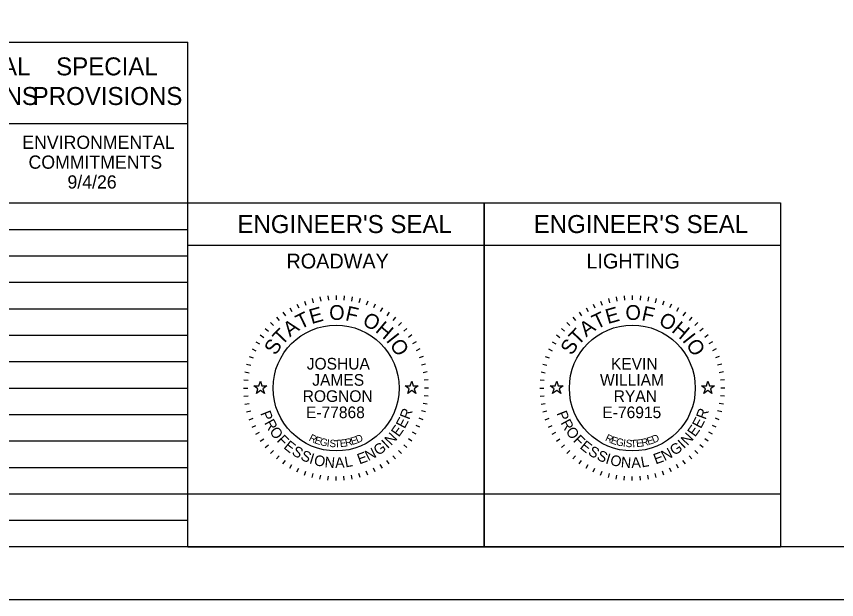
# Model space of a CAD drawing. Extents: x 0 to 34, y 0 to 22.
# Drawn here: x 21.98 to 29.73, y 0 to 5.51 of the extents above; entities that cross this region are included whole.
import ezdxf

# ---------------------------------------------------------------- set-up
doc = ezdxf.new("R2010")
doc.units = 0
for name, color, linetype in [('SH_Border', 7, 'Continuous'), ('SH_Cut_Line', 7, 'Continuous'), ('SH_Data', 7, 'Continuous'), ('SH_Seal', 7, 'Continuous'), ('SH_Text', 7, 'Continuous')]:
    doc.layers.add(name, color=color, linetype=linetype)

msp = doc.modelspace()

# ---------------------------------------------------------------- linework, layer by layer
at = {"layer": 'SH_Border'}
msp.add_lwpolyline([(1.5, 21.5), (33.5, 21.5), (33.5, 0.5), (1.5, 0.5)], close=True, dxfattribs=at)
at = {"layer": 'SH_Cut_Line'}
msp.add_lwpolyline([(0, 0), (34, 0), (34, 22), (0, 22)], close=True, dxfattribs=at)
at = {"layer": 'SH_Data'}
for p, q in [((10.15, 5.2708), (23.6, 5.2708)), ((23.6, 0.5), (23.6, 5.2708)), ((10.15, 4.5), (23.6, 4.5)), ((10.15, 3.75), (23.6, 3.75)), ((23.6, 0.5), (23.6, 3.75)), ((23.6, 3.75), (26.4, 3.75)), ((26.4, 3.75), (26.4, 0.5)), ((26.4, 0.5), (26.4, 3.75)), ((26.4, 3.75), (29.2, 3.75)), ((29.2, 3.75), (29.2, 0.5)), ((10.15, 3.5), (23.6, 3.5)), ((23.6, 3.35), (26.4, 3.35)), ((26.4, 3.35), (29.2, 3.35)), ((10.15, 3.25), (23.6, 3.25)), ((10.15, 3), (23.6, 3)), ((10.15, 2.75), (23.6, 2.75)), ((10.15, 2.5), (23.6, 2.5)), ((10.15, 2.25), (23.6, 2.25)), ((10.15, 2), (23.6, 2)), ((10.15, 1.75), (23.6, 1.75)), ((10.15, 1.5), (23.6, 1.5)), ((10.15, 1.25), (23.6, 1.25)), ((10.15, 1), (23.6, 1)), ((10.15, 0.75), (23.6, 0.75)), ((23.6, 0.5), (26.4, 0.5)), ((26.4, 0.5), (29.2, 0.5))]:
    msp.add_line(p, q, dxfattribs=at)
for points in [[(23.6, 0.5), (23.6, 1), (26.4, 1), (26.4, 0.5)], [(26.4, 0.5), (26.4, 1), (29.2, 1), (29.2, 0.5)]]:
    msp.add_lwpolyline(points, close=True, dxfattribs=at)
at = {"layer": 'SH_Seal'}
for p, q in [((24.9237, 2.8717), (24.9272, 2.8318)), ((25, 2.875), (25, 2.835)), ((25.0763, 2.8717), (25.0728, 2.8318)), ((27.7237, 2.8717), (27.7272, 2.8318)), ((27.8, 2.875), (27.8, 2.835)), ((27.8763, 2.8717), (27.8728, 2.8318)), ((24.6302, 2.793), (24.6471, 2.7568)), ((24.7007, 2.8222), (24.7144, 2.7846)), ((24.7735, 2.8452), (24.7839, 2.8065)), ((24.8481, 2.8617), (24.855, 2.8223)), ((25.1519, 2.8617), (25.145, 2.8223)), ((25.2265, 2.8452), (25.2161, 2.8065)), ((25.2993, 2.8222), (25.2856, 2.7846)), ((25.3698, 2.793), (25.3529, 2.7568)), ((27.4302, 2.793), (27.4471, 2.7568)), ((27.5007, 2.8222), (27.5144, 2.7846)), ((27.5735, 2.8452), (27.5839, 2.8065)), ((27.6481, 2.8617), (27.655, 2.8223)), ((27.9519, 2.8617), (27.945, 2.8223)), ((28.0265, 2.8452), (28.0161, 2.8065)), ((28.0993, 2.8222), (28.0856, 2.7846)), ((28.1698, 2.793), (28.1529, 2.7568)), ((24.4981, 2.7168), (24.5211, 2.684)), ((24.5625, 2.7578), (24.5825, 2.7231)), ((25.4375, 2.7578), (25.4175, 2.7231)), ((25.5019, 2.7168), (25.4789, 2.684)), ((27.2981, 2.7168), (27.3211, 2.684)), ((27.3625, 2.7578), (27.3825, 2.7231)), ((28.2375, 2.7578), (28.2175, 2.7231)), ((28.3019, 2.7168), (28.2789, 2.684)), ((24.4376, 2.6703), (24.4633, 2.6396)), ((25.5624, 2.6703), (25.5367, 2.6396)), ((27.2376, 2.6703), (27.2633, 2.6396)), ((28.3624, 2.6703), (28.3367, 2.6396)), ((24.3297, 2.5624), (24.3604, 2.5367)), ((24.3813, 2.6187), (24.4096, 2.5904)), ((25.6187, 2.6187), (25.5904, 2.5904)), ((25.6703, 2.5624), (25.6396, 2.5367)), ((27.1297, 2.5624), (27.1604, 2.5367)), ((27.1813, 2.6187), (27.2096, 2.5904)), ((28.4187, 2.6187), (28.3904, 2.5904)), ((28.4703, 2.5624), (28.4396, 2.5367)), ((24.2832, 2.5019), (24.316, 2.4789)), ((25.7168, 2.5019), (25.684, 2.4789)), ((27.0832, 2.5019), (27.116, 2.4789)), ((28.5168, 2.5019), (28.484, 2.4789)), ((24.2422, 2.4375), (24.2769, 2.4175)), ((25.7578, 2.4375), (25.7231, 2.4175)), ((27.0422, 2.4375), (27.0769, 2.4175)), ((28.5578, 2.4375), (28.5231, 2.4175)), ((24.207, 2.3698), (24.2432, 2.3529)), ((25.793, 2.3698), (25.7568, 2.3529)), ((27.007, 2.3698), (27.0432, 2.3529)), ((28.593, 2.3698), (28.5568, 2.3529)), ((24.1778, 2.2993), (24.2154, 2.2856)), ((25.8222, 2.2993), (25.7846, 2.2856)), ((26.9778, 2.2993), (27.0154, 2.2856)), ((28.6222, 2.2993), (28.5846, 2.2856)), ((24.1548, 2.2265), (24.1935, 2.2161)), ((25.8452, 2.2265), (25.8065, 2.2161)), ((26.9548, 2.2265), (26.9935, 2.2161)), ((28.6452, 2.2265), (28.6065, 2.2161)), ((24.1383, 2.1519), (24.1777, 2.145)), ((25.8617, 2.1519), (25.8223, 2.145)), ((26.9383, 2.1519), (26.9777, 2.145)), ((28.6617, 2.1519), (28.6223, 2.145)), ((24.1283, 2.0763), (24.1682, 2.0728)), ((25.8717, 2.0763), (25.8318, 2.0728)), ((26.9283, 2.0763), (26.9682, 2.0728)), ((28.6717, 2.0763), (28.6318, 2.0728)), ((24.125, 2), (24.165, 2)), ((25.875, 2), (25.835, 2)), ((26.925, 2), (26.965, 2)), ((28.675, 2), (28.635, 2)), ((24.1283, 1.9237), (24.1682, 1.9272)), ((25.8717, 1.9237), (25.8318, 1.9272)), ((26.9283, 1.9237), (26.9682, 1.9272)), ((28.6717, 1.9237), (28.6318, 1.9272)), ((24.1383, 1.8481), (24.1777, 1.855)), ((24.1548, 1.7735), (24.1935, 1.7839)), ((25.8452, 1.7735), (25.8065, 1.7839)), ((25.8617, 1.8481), (25.8223, 1.855)), ((26.9383, 1.8481), (26.9777, 1.855)), ((26.9548, 1.7735), (26.9935, 1.7839)), ((28.6452, 1.7735), (28.6065, 1.7839)), ((28.6617, 1.8481), (28.6223, 1.855)), ((24.1778, 1.7007), (24.2154, 1.7144)), ((25.8222, 1.7007), (25.7846, 1.7144)), ((26.9778, 1.7007), (27.0154, 1.7144)), ((28.6222, 1.7007), (28.5846, 1.7144)), ((24.207, 1.6302), (24.2432, 1.6471)), ((25.793, 1.6302), (25.7568, 1.6471)), ((27.007, 1.6302), (27.0432, 1.6471)), ((28.593, 1.6302), (28.5568, 1.6471)), ((24.2422, 1.5625), (24.2769, 1.5825)), ((25.7578, 1.5625), (25.7231, 1.5825)), ((27.0422, 1.5625), (27.0769, 1.5825)), ((28.5578, 1.5625), (28.5231, 1.5825)), ((24.2832, 1.4981), (24.316, 1.5211)), ((25.7168, 1.4981), (25.684, 1.5211)), ((27.0832, 1.4981), (27.116, 1.5211)), ((28.5168, 1.4981), (28.484, 1.5211)), ((24.3297, 1.4376), (24.3604, 1.4633)), ((24.3813, 1.3813), (24.4096, 1.4096)), ((25.6187, 1.3813), (25.5904, 1.4096)), ((25.6703, 1.4376), (25.6396, 1.4633)), ((27.1297, 1.4376), (27.1604, 1.4633)), ((27.1813, 1.3813), (27.2096, 1.4096)), ((28.4187, 1.3813), (28.3904, 1.4096)), ((28.4703, 1.4376), (28.4396, 1.4633)), ((24.4376, 1.3297), (24.4633, 1.3604)), ((25.5624, 1.3297), (25.5367, 1.3604)), ((27.2376, 1.3297), (27.2633, 1.3604)), ((28.3624, 1.3297), (28.3367, 1.3604)), ((24.4981, 1.2832), (24.5211, 1.316)), ((24.5625, 1.2422), (24.5825, 1.2769)), ((24.6302, 1.207), (24.6471, 1.2432)), ((25.3698, 1.207), (25.3529, 1.2432)), ((25.4375, 1.2422), (25.4175, 1.2769)), ((25.5019, 1.2832), (25.4789, 1.316)), ((27.2981, 1.2832), (27.3211, 1.316)), ((27.3625, 1.2422), (27.3825, 1.2769)), ((27.4302, 1.207), (27.4471, 1.2432)), ((28.1698, 1.207), (28.1529, 1.2432)), ((28.2375, 1.2422), (28.2175, 1.2769)), ((28.3019, 1.2832), (28.2789, 1.316)), ((24.7007, 1.1778), (24.7144, 1.2154)), ((24.7735, 1.1548), (24.7839, 1.1935)), ((24.8481, 1.1383), (24.855, 1.1777)), ((24.9237, 1.1283), (24.9272, 1.1682)), ((25, 1.125), (25, 1.165)), ((25.0763, 1.1283), (25.0728, 1.1682)), ((25.1519, 1.1383), (25.145, 1.1777)), ((25.2265, 1.1548), (25.2161, 1.1935)), ((25.2993, 1.1778), (25.2856, 1.2154)), ((27.5007, 1.1778), (27.5144, 1.2154)), ((27.5735, 1.1548), (27.5839, 1.1935)), ((27.6481, 1.1383), (27.655, 1.1777)), ((27.7237, 1.1283), (27.7272, 1.1682)), ((27.8, 1.125), (27.8, 1.165)), ((27.8763, 1.1283), (27.8728, 1.1682)), ((27.9519, 1.1383), (27.945, 1.1777)), ((28.0265, 1.1548), (28.0161, 1.1935)), ((28.0993, 1.1778), (28.0856, 1.2154))]:
    msp.add_line(p, q, dxfattribs=at)
for points in [[(24.2236, 2.02), (24.2705, 2.02), (24.285, 2.0645), (24.2995, 2.02), (24.3464, 2.02), (24.3085, 1.9924), (24.323, 1.9478), (24.285, 1.9754), (24.247, 1.9478), (24.2615, 1.9924)], [(25.6536, 2.02), (25.7005, 2.02), (25.715, 2.0645), (25.7295, 2.02), (25.7764, 2.02), (25.7385, 1.9924), (25.753, 1.9478), (25.715, 1.9754), (25.677, 1.9478), (25.6915, 1.9924)], [(27.0236, 2.02), (27.0705, 2.02), (27.085, 2.0645), (27.0995, 2.02), (27.1464, 2.02), (27.1085, 1.9924), (27.123, 1.9478), (27.085, 1.9754), (27.047, 1.9478), (27.0615, 1.9924)], [(28.4536, 2.02), (28.5005, 2.02), (28.515, 2.0645), (28.5295, 2.02), (28.5764, 2.02), (28.5385, 1.9924), (28.553, 1.9478), (28.515, 1.9754), (28.477, 1.9478), (28.4915, 1.9924)]]:
    msp.add_lwpolyline(points, close=True, dxfattribs=at)
for centre in [(25, 2), (27.8, 2)]:
    msp.add_circle(centre, 0.595, dxfattribs=at)

# ---------------------------------------------------------------- texts
at = {"layer": 'SH_Data'}
for s, height, p in [("ENGINEER'S SEAL", 0.17, (24.0676, 3.465)), ("ENGINEER'S SEAL", 0.17, (26.8676, 3.465)), ('ROADWAY', 0.14, (24.5311, 3.13)), ('LIGHTING', 0.14, (27.366, 3.13))]:
    msp.add_text(s, height=height, dxfattribs=at).set_placement(p)
at = {"layer": 'SH_Seal'}
for s, height, rotation, p in [('T', 0.14, 25.71674, (24.6616, 2.5518)), ('E', 0.14, 15.75706, (24.7684, 2.6038)), ('O', 0.14, 359.78119, (24.9347, 2.6443)), ('F', 0.14, 347.43619, (25.0811, 2.6417)), ('T', 0.14, 25.71674, (27.4616, 2.5518)), ('E', 0.14, 15.75706, (27.5684, 2.6038)), ('O', 0.14, 359.78119, (27.7347, 2.6443)), ('F', 0.14, 347.43619, (27.8811, 2.6417)), ('O', 0.14, 332.25863, (25.2398, 2.6015)), ('O', 0.14, 332.25863, (28.0398, 2.6015)), ('T', 0.14, 46.4344, (24.4883, 2.3964)), ('A', 0.14, 36.47472, (24.5634, 2.4781)), ('H', 0.14, 319.91363, (25.3632, 2.5361)), ('T', 0.14, 46.4344, (27.2883, 2.3964)), ('A', 0.14, 36.47472, (27.3634, 2.4781)), ('H', 0.14, 319.91363, (28.1632, 2.5361)), ('I', 0.14, 308.36695, (25.4665, 2.4483)), ('I', 0.14, 308.36695, (28.2665, 2.4483)), ('S', 0.14, 57.19238, (24.4281, 2.3014)), ('O', 0.14, 303.14906, (25.5021, 2.4089)), ('S', 0.14, 57.19238, (27.2281, 2.3014)), ('O', 0.14, 303.14906, (28.3021, 2.4089)), ('P', 0.1, 291.49398, (24.2823, 1.7621)), ('R', 0.1, 69.23216, (25.6919, 1.6954)), ('P', 0.1, 291.49398, (27.0823, 1.7621)), ('R', 0.1, 69.23216, (28.4919, 1.6954)), ('R', 0.1, 298.73106, (24.319, 1.6717)), ('E', 0.1, 61.99508, (25.6476, 1.6098)), ('R', 0.1, 298.73106, (27.119, 1.6717)), ('E', 0.1, 61.99508, (28.4476, 1.6098)), ('E', 0.1, 54.75801, (25.5933, 1.5314)), ('E', 0.1, 54.75801, (28.3933, 1.5314)), ('O', 0.1, 306.46664, (24.3655, 1.5883)), ('F', 0.1, 314.7068, (24.4343, 1.4983)), ('R', 0.07, 334.48695, (24.7375, 1.5051)), ('D', 0.07, 23.30524, (25.201, 1.477)), ('N', 0.1, 47.02243, (25.5202, 1.4508)), ('O', 0.1, 306.46664, (27.1655, 1.5883)), ('F', 0.1, 314.7068, (27.2343, 1.4983)), ('R', 0.07, 334.48695, (27.5375, 1.5051)), ('D', 0.07, 23.30524, (28.001, 1.477)), ('N', 0.1, 47.02243, (28.3202, 1.4508)), ('E', 0.1, 321.43929, (24.4978, 1.4348)), ('E', 0.07, 341.03996, (24.7906, 1.4801)), ('G', 0.07, 347.47515, (24.8414, 1.4618)), ('I', 0.07, 353.78581, (24.9091, 1.4468)), ('S', 0.07, 356.89262, (24.9358, 1.4429)), ('T', 0.07, 3.00609, (24.9857, 1.4387)), ('E', 0.07, 6.01169, (25.0389, 1.4412)), ('R', 0.07, 11.91844, (25.0925, 1.4474)), ('E', 0.07, 17.68363, (25.1498, 1.4602)), ('G', 0.1, 35.04687, (25.3981, 1.357)), ('I', 0.1, 43.28703, (25.4868, 1.4214)), ('E', 0.1, 321.43929, (27.2978, 1.4348)), ('E', 0.07, 341.03996, (27.5906, 1.4801)), ('G', 0.07, 347.47515, (27.6414, 1.4618)), ('I', 0.07, 353.78581, (27.7091, 1.4468)), ('S', 0.07, 356.89262, (27.7358, 1.4429)), ('T', 0.07, 3.00609, (27.7857, 1.4387)), ('E', 0.07, 6.01169, (27.8389, 1.4412)), ('R', 0.07, 11.91844, (27.8925, 1.4474)), ('E', 0.07, 17.68363, (27.9498, 1.4602)), ('G', 0.1, 35.04687, (28.1981, 1.357)), ('I', 0.1, 43.28703, (28.2868, 1.4214)), ('S', 0.1, 328.67637, (24.5743, 1.3752)), ('S', 0.1, 335.91345, (24.6564, 1.3266)), ('E', 0.1, 20.07421, (25.2212, 1.277)), ('N', 0.1, 27.31129, (25.3045, 1.3075)), ('S', 0.1, 328.67637, (27.3743, 1.3752)), ('S', 0.1, 335.91345, (27.4564, 1.3266)), ('E', 0.1, 20.07421, (28.0212, 1.277)), ('N', 0.1, 27.31129, (28.1045, 1.3075)), ('I', 0.1, 343.15053, (24.7406, 1.2897)), ('O', 0.1, 346.88592, (24.7839, 1.2751)), ('N', 0.1, 355.12608, (24.8888, 1.2517)), ('A', 0.1, 2.86166, (24.9923, 1.2437)), ('L', 0.1, 10.09874, (25.0894, 1.249)), ('I', 0.1, 343.15053, (27.5406, 1.2897)), ('O', 0.1, 346.88592, (27.5839, 1.2751)), ('N', 0.1, 355.12608, (27.6888, 1.2517)), ('A', 0.1, 2.86166, (27.7923, 1.2437)), ('L', 0.1, 10.09874, (27.8894, 1.249))]:
    msp.add_text(s, height=height, rotation=rotation, dxfattribs=at).set_placement(p)
for s, p in [('JOSHUA', (24.7228, 2.1749)), ('KEVIN', (27.5975, 2.1749)), ('JAMES', (24.775, 2.0216)), ('WILLIAM', (27.4946, 2.0216)), ('ROGNON', (24.6843, 1.8684)), ('RYAN', (27.6241, 1.8684)), ('E-77868', (24.7157, 1.7151)), ('E-76915', (27.5173, 1.7151))]:
    msp.add_text(s, height=0.11, dxfattribs=at).set_placement(p)
at = {"layer": 'SH_Text'}
for s, height, p in [('SUPPLEMENTAL', 0.17, (20.2925, 4.9554)), ('SPECIAL', 0.17, (22.3542, 4.9554)), ('SPECIFICATIONS', 0.17, (20.2871, 4.6754)), ('PROVISIONS', 0.17, (22.1323, 4.6754)), ('ENVIRONMENTAL ', 0.125, (22.0343, 4.2605)), ('COMMITMENTS', 0.125, (22.0933, 4.073)), ('9/4/26', 0.125, (22.4613, 3.8855))]:
    msp.add_text(s, height=height, dxfattribs=at).set_placement(p)

doc.saveas('drawing.dxf')
